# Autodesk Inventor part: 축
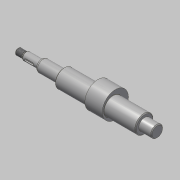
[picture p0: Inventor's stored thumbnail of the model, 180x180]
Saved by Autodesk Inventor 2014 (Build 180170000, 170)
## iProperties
Created: 2015-12
Part Number: 축
Document SubType Name: Modeling
Designer: mdu
Density: 7.86 g/cm^3
Material: 강철, 연강
Appearance: 강철
Author: mdu
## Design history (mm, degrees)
sketch "스케치1"
  geometry: L1 (62, 100.9)-(62, 67.1) reference; L2 (51, 101.2)-(51, 84) reference; L3 (-51, 84)-(-51, 101.2) reference; L4 (-62, 67.1)-(-62, 100.9) reference; L5 (-51.6, 91.5)-(-61.4, 91.5) reference; L6 (51.6, 91.5)-(61.4, 91.5) reference; L7 (67, 84)-(-109, 84); L8 (-77, 64.201)-(-77, 103.799) reference; L9 (67, 84)-(67, 91.5); L10 (67, 91.5)-(51, 91.5); L11 (51, 91.5)-(51, 95.5); L12 (51, 95.5)-(-51, 95.5); L13 (-51, 95.5)-(-51, 91.5); L14 (-51, 91.5)-(-79, 91.5); L15 (-79, 91.5)-(-79, 89); L16 (-79, 89)-(-99, 89); L17 (-99, 89)-(-99, 87); L18 (-100.5, 88)-(-109, 88); L19 (-109, 88)-(-109, 84); L20 (-99, 87)-(-100.5, 87); L21 (-100.5, 87)-(-100.5, 88); 2 further points
  constraints: 32 end point, 7 parallel, 6 point on line, 5 perpendicular, 2 collinear, 2 horizontal, 1 midpoint, 4 other
  dimensions: "d0" = 5 distance from line of L7.start L1; "d2" = 2 distance between parallel lines of L15 L8; "d3" = 23 diameter of L12 L7; "d4" = 10 diameter of L16 L7; "d5" = 1.5 distance of L17.end L20.end; "d6" = 6 diameter of L20 L7; "d7" = 20 distance of L15.end L16.end; "d8" = 10 distance between parallel lines of L17 L19; "d9" = 8 diameter of L18 L7
revolve "회전1" sketch "스케치1" stored, may be unused: angle "d10" = 90 deg
sketch "스케치2"
  geometry: C1 r 11.5 at (84, 0) reference; C2 r 11.5 at (84, 0) reference; C3 r 16.5 at (87, 0); 1 further point
  constraints: 1 centre point, 1 horizontal alignment
  dimensions: "d11" = 33 diameter of C3; "d12" = 3 distance of C3.centre C1.centre
extrude "돌출1" join sketch "스케치2" stored distance "d13" = 22; taper "d14" = 0 deg
chamfer "모따기1" distance "d15" = 1; stored, may be unused: second distance "d16" = 2, angle "d17" = 45 deg
feature "스레드1" dims "d18" = 10, "d19" = 0
node "작업 평면1"
sketch "스케치3"
  geometry: L1 (-5.5, -1.5)-(3.5, -1.5); L2 (3.5, 1.5)-(-5.5, 1.5); L3 (-10, -4)-(-10, 4) reference; A1 r 1.5 centre (3.5, 0) between (3.5, -1.5) and (3.5, 1.5); A2 r 1.5 centre (-5.5, 0) between (-5.5, 1.5) and (-5.5, -1.5); 2 further points
  constraints: 4 end point, 4 point on circle, 4 tangent, 2 centre point, 1 horizontal, 1 horizontal alignment, 1 midpoint, 1 parallel
  dimensions: "d20" = 3 distance between parallel lines of L1 L2; "d21" = 12 dimension on A1 A2; "d22" = 3 distance edge to line of A2 L3
extrude "돌출2" cut sketch "스케치3" distance "d23" = 1.8; taper "d24" = 0 deg
fillet "모깎기1" dims "d25" = 0.3
fillet "모깎기2" dims "d26" = 3
node "솔리드1"
node "참조1"
node "참조2"
node "참조3"
node "참조4"
node "참조5"
node "투영된 루프1"
